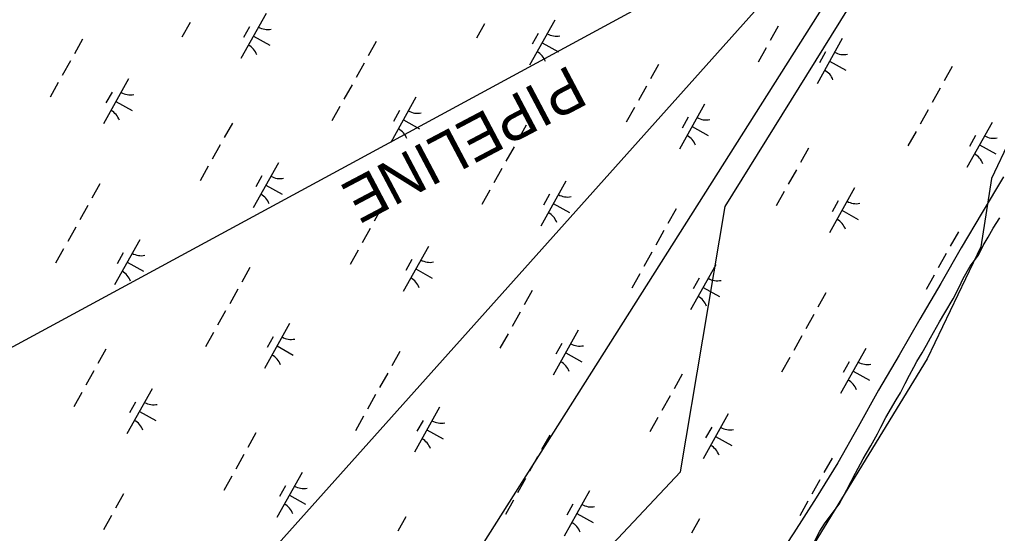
# Model space of a CAD drawing. Extents: x 3923531 to 3943530, y 207391 to 229799.
# Drawn here: x 3933623 to 3934571, y 218625 to 219123 of the extents above; entities that cross this region are included whole.
import ezdxf

# ---------------------------------------------------------------- set-up
doc = ezdxf.new("R2010")
doc.units = 0
for name, color, linetype in [('V-RIVR-EDGE', 7, 'Continuous'), ('V-RRAP-FSHR', 7, 'Continuous'), ('V-UTIL-IDEN', 7, 'Continuous'), ('V-UTIL-LINE', 7, 'Continuous'), ('V-WETL-SWMP', 7, 'Continuous')]:
    doc.layers.add(name, color=color, linetype=linetype)

msp = doc.modelspace()

# ---------------------------------------------------------------- linework, layer by layer
at = {"layer": 'V-RIVR-EDGE'}
msp.add_lwpolyline([(3934582.61, 219006.45), (3934564.92, 218968.73), (3934554.32, 218902.72), (3934502.45, 218794.28), (3934376.33, 218588)], dxfattribs=at)
at = {"layer": 'V-RRAP-FSHR'}
msp.add_lwpolyline([(3934576.29, 218970.39), (3934555.88, 218935.98), (3934535.47, 218901.58), (3934515.64, 218867.18), (3934495.48, 218832.55), (3934475.21, 218797.82), (3934455.37, 218763.92), (3934435.63, 218728.3), (3934415.91, 218693.5), (3934394.97, 218659.43), (3934373.4, 218625.75), (3934351.84, 218592.57)], dxfattribs=at)
at = {"layer": 'V-UTIL-LINE'}
for points in [[(3936636.37, 224015.9), (3936525.62, 224056.17), (3935321.28, 220766.16), (3935347.69, 220401.84), (3934871.29, 219561.15), (3934439.51, 219247.4), (3932085.86, 216616.76), (3928247.61, 212430.32)], [(3934948.13, 219998.51), (3933937.95, 218403.55), (3930512.92, 214727.55), (3928293.59, 212405.31)], [(3936739.29, 218357.68), (3936622.11, 218414.56), (3934986.4, 219548.1), (3933485.3, 218734.77), (3932851.99, 218820.89)], [(3928303.68, 212396.77), (3930529.58, 214712.48), (3934263.4, 218684.83), (3934306.77, 218941.79), (3934562.09, 219352.8), (3934805.1, 219208.23)]]:
    msp.add_lwpolyline(points, dxfattribs=at)
at = {"layer": 'V-WETL-SWMP'}
for p, q in [((3933862.12, 219128.66), (3933837.73, 219085.01)), ((3933788.45, 219119.9), (3933780.65, 219105.93)), ((3934073.65, 219118.64), (3934065.85, 219104.68)), ((3934141.74, 219122.18), (3934117.35, 219078.53)), ((3934358.19, 219116.56), (3934350.39, 219102.59)), ((3933846.12, 219115.84), (3933840.26, 219105.36)), ((3934125.74, 219109.36), (3934119.88, 219098.88)), ((3933684.24, 219103.71), (3933676.44, 219089.74)), ((3933849.93, 219106.83), (3933865.64, 219098.06)), ((3933968.78, 219101.63), (3933960.98, 219087.66)), ((3934129.55, 219100.36), (3934145.26, 219091.58)), ((3934420.15, 219104.37), (3934395.77, 219060.72)), ((3934346.49, 219095.61), (3934338.68, 219081.64)), ((3934404.15, 219091.55), (3934398.3, 219081.07)), ((3933672.54, 219082.76), (3933664.73, 219068.79)), ((3933957.08, 219080.68), (3933949.27, 219066.71)), ((3934242.27, 219079.42), (3934234.47, 219065.46)), ((3934407.96, 219082.55), (3934423.67, 219073.77)), ((3934526.82, 219077.34), (3934519.01, 219063.37)), ((3933660.83, 219061.81), (3933653.03, 219047.84)), ((3933728.92, 219065.35), (3933704.53, 219021.7)), ((3933945.37, 219059.72), (3933937.57, 219045.76)), ((3933712.92, 219052.52), (3933707.06, 219042.05)), ((3934230.57, 219058.47), (3934222.77, 219044.5)), ((3934515.11, 219056.39), (3934507.31, 219042.42)), ((3933716.73, 219043.52), (3933732.44, 219034.74)), ((3934007.33, 219047.54), (3933982.95, 219003.89)), ((3934286.95, 219041.06), (3934262.57, 218997.41)), ((3933933.67, 219038.77), (3933925.86, 219024.8)), ((3933991.33, 219034.71), (3933985.48, 219024.24)), ((3934218.86, 219037.52), (3934211.06, 219023.55)), ((3934503.41, 219035.44), (3934495.6, 219021.47)), ((3933829.45, 219022.59), (3933821.65, 219008.62)), ((3933995.14, 219025.71), (3934010.85, 219016.93)), ((3934270.95, 219028.23), (3934265.1, 219017.76)), ((3934565.37, 219023.25), (3934540.98, 218979.6)), ((3934114, 219020.5), (3934106.19, 219006.54)), ((3934274.76, 219019.23), (3934290.47, 219010.45)), ((3934491.7, 219014.48), (3934483.9, 219000.52)), ((3934549.36, 219010.42), (3934543.51, 218999.95)), ((3933817.75, 219001.64), (3933809.95, 218987.67)), ((3934102.29, 218999.55), (3934094.49, 218985.58)), ((3934387.49, 218998.3), (3934379.68, 218984.33)), ((3934553.17, 219001.42), (3934568.89, 218992.64)), ((3933874.13, 218984.22), (3933849.75, 218940.57)), ((3933806.04, 218980.68), (3933798.24, 218966.72)), ((3934090.59, 218978.6), (3934082.78, 218964.63)), ((3934375.78, 218977.35), (3934367.98, 218963.38)), ((3933858.13, 218971.4), (3933852.28, 218960.92)), ((3934152.55, 218966.41), (3934128.16, 218922.76)), ((3933701.18, 218963.67), (3933693.37, 218949.7)), ((3933861.94, 218962.4), (3933877.65, 218953.62)), ((3934078.88, 218957.65), (3934071.08, 218943.68)), ((3934364.08, 218956.4), (3934356.27, 218942.43)), ((3934432.17, 218959.93), (3934407.78, 218916.28)), ((3934136.54, 218953.59), (3934130.69, 218943.11)), ((3934416.16, 218947.11), (3934410.31, 218936.63)), ((3933689.47, 218942.72), (3933681.67, 218928.75)), ((3933974.67, 218941.46), (3933966.86, 218927.5)), ((3934140.35, 218944.59), (3934156.07, 218935.81)), ((3934259.21, 218939.38), (3934251.41, 218925.41)), ((3934419.97, 218938.11), (3934435.69, 218929.33)), ((3934566.31, 218920.74), (3934572.99, 218930.64)), ((3933677.77, 218921.76), (3933669.96, 218907.8)), ((3933962.96, 218920.51), (3933955.16, 218906.54)), ((3934247.51, 218918.43), (3934239.7, 218904.46)), ((3934561.43, 218912.02), (3934566.31, 218920.74)), ((3933739.73, 218909.58), (3933715.34, 218865.93)), ((3934532.7, 218917.18), (3934524.9, 218903.21)), ((3934556.76, 218903.89), (3934561.43, 218912.02)), ((3933666.06, 218900.81), (3933658.26, 218886.84)), ((3933951.26, 218899.56), (3933943.45, 218885.59)), ((3934019.35, 218903.1), (3933994.96, 218859.45)), ((3934552.09, 218894.77), (3934556.76, 218903.89)), ((3933723.72, 218896.75), (3933717.87, 218886.28)), ((3934003.34, 218890.27), (3933997.49, 218879.8)), ((3934235.8, 218897.48), (3934228, 218883.51)), ((3934521, 218896.22), (3934513.19, 218882.26)), ((3934544.2, 218883.89), (3934552.09, 218894.77)), ((3933727.53, 218887.75), (3933743.25, 218878.97)), ((3933846.39, 218882.54), (3933838.59, 218868.58)), ((3934007.15, 218881.27), (3934022.87, 218872.49)), ((3934297.76, 218885.29), (3934273.37, 218841.64)), ((3934537.3, 218872), (3934544.2, 218883.89)), ((3934224.1, 218876.52), (3934216.29, 218862.56)), ((3934281.76, 218872.46), (3934275.91, 218861.99)), ((3934509.29, 218875.27), (3934501.49, 218861.3)), ((3934533.42, 218863.47), (3934537.3, 218872)), ((3933834.69, 218861.59), (3933826.88, 218847.62)), ((3934285.57, 218863.46), (3934301.28, 218854.68)), ((3934527.72, 218852.36), (3934533.42, 218863.47)), ((3934119.88, 218860.34), (3934112.08, 218846.37)), ((3934404.42, 218858.26), (3934396.62, 218844.29)), ((3934519.61, 218838.89), (3934527.72, 218852.36)), ((3933822.98, 218840.64), (3933815.18, 218826.67)), ((3934108.18, 218839.39), (3934100.37, 218825.42)), ((3934392.72, 218837.3), (3934384.92, 218823.34)), ((3934514.54, 218830.17), (3934519.61, 218838.89)), ((3933884.94, 218828.45), (3933860.55, 218784.8)), ((3934505.8, 218814.51), (3934514.54, 218830.17)), ((3933811.28, 218819.69), (3933803.47, 218805.72)), ((3933868.94, 218815.63), (3933863.09, 218805.15)), ((3934096.47, 218818.44), (3934088.67, 218804.47)), ((3934164.56, 218821.97), (3934140.17, 218778.32)), ((3934381.01, 218816.35), (3934373.21, 218802.38)), ((3934501.74, 218807.38), (3934505.8, 218814.51)), ((3933872.75, 218806.63), (3933888.46, 218797.85)), ((3934148.56, 218809.15), (3934142.7, 218798.67)), ((3934442.97, 218804.16), (3934418.59, 218760.51)), ((3934497.48, 218799.85), (3934501.74, 218807.38)), ((3933707.06, 218803.5), (3933699.26, 218789.54)), ((3933991.6, 218801.42), (3933983.8, 218787.45)), ((3934152.37, 218800.15), (3934168.08, 218791.37)), ((3934369.31, 218795.4), (3934361.51, 218781.43)), ((3934492.61, 218791.53), (3934497.48, 218799.85)), ((3934426.97, 218791.34), (3934421.12, 218780.86)), ((3934485.49, 218778.24), (3934489.56, 218785.98)), ((3934489.56, 218785.98), (3934492.61, 218791.53)), ((3933695.36, 218782.55), (3933687.55, 218768.58)), ((3933979.9, 218780.47), (3933972.1, 218766.5)), ((3934265.09, 218779.22), (3934257.29, 218765.25)), ((3934430.78, 218782.34), (3934446.49, 218773.56)), ((3934481.03, 218770.32), (3934485.49, 218778.24)), ((3934476.55, 218761.19), (3934481.03, 218770.32)), ((3933683.65, 218761.6), (3933675.85, 218747.63)), ((3933751.74, 218765.14), (3933727.35, 218721.49)), ((3933968.19, 218759.52), (3933960.39, 218745.55)), ((3934253.39, 218758.26), (3934245.59, 218744.3)), ((3934472.29, 218754.46), (3934476.55, 218761.19)), ((3933735.74, 218752.31), (3933729.88, 218741.84)), ((3934030.15, 218747.33), (3934005.77, 218703.68)), ((3934462.34, 218737.22), (3934472.29, 218754.46)), ((3933739.55, 218743.31), (3933755.26, 218734.53)), ((3933956.49, 218738.56), (3933948.69, 218724.59)), ((3934309.77, 218740.85), (3934285.39, 218697.2)), ((3934014.15, 218734.5), (3934008.3, 218724.03)), ((3934241.68, 218737.31), (3934233.88, 218723.34)), ((3934457.66, 218727.9), (3934462.34, 218737.22)), ((3933852.27, 218722.38), (3933844.47, 218708.41)), ((3934017.96, 218725.5), (3934033.68, 218716.72)), ((3934136.82, 218720.3), (3934129.01, 218706.33)), ((3934293.77, 218728.03), (3934287.92, 218717.55)), ((3934297.58, 218719.02), (3934313.29, 218710.25)), ((3934447.91, 218709.86), (3934454.41, 218721.55)), ((3934454.41, 218721.55), (3934457.66, 218727.9)), ((3934440.6, 218697.38), (3934447.91, 218709.86)), ((3933840.57, 218701.43), (3933832.77, 218687.46)), ((3934125.11, 218699.34), (3934117.31, 218685.38)), ((3934410.31, 218698.09), (3934402.51, 218684.12)), ((3934433.08, 218683.3), (3934440.6, 218697.38)), ((3933896.95, 218684.01), (3933872.57, 218640.36)), ((3934424.54, 218667.44), (3934433.08, 218683.3)), ((3933828.86, 218680.48), (3933821.06, 218666.51)), ((3934113.41, 218678.39), (3934105.6, 218664.42)), ((3934398.6, 218677.14), (3934390.8, 218663.17)), ((3933724, 218663.46), (3933716.19, 218649.49)), ((3933880.95, 218671.19), (3933875.1, 218660.71)), ((3933884.76, 218662.19), (3933900.47, 218653.41)), ((3934175.37, 218666.2), (3934150.98, 218622.55)), ((3934417.22, 218653.56), (3934424.54, 218667.44)), ((3934101.7, 218657.44), (3934093.9, 218643.47)), ((3934159.37, 218653.38), (3934153.51, 218642.9)), ((3934386.9, 218656.19), (3934379.1, 218642.22)), ((3934410.35, 218644.26), (3934417.22, 218653.56)), ((3934163.17, 218644.38), (3934178.89, 218635.6)), ((3934402.87, 218634.37), (3934410.35, 218644.26)), ((3933712.29, 218642.51), (3933704.49, 218628.54)), ((3933997.49, 218641.26), (3933989.69, 218627.29)), ((3934282.03, 218639.17), (3934274.23, 218625.2)), ((3934398.61, 218627.24), (3934402.87, 218634.37)), ((3934393.32, 218617.33), (3934398.61, 218627.24))]:
    msp.add_line(p, q, dxfattribs=at)
for centre, start, end in [((3933863.6, 219130.83), 240.03808, 281.58174), ((3934143.22, 219124.36), 240.03808, 281.58174), ((3933836.66, 219082.61), 20.03808, 61.58174), ((3934116.28, 219076.13), 20.03808, 61.58174), ((3934421.64, 219106.54), 240.03808, 281.58174), ((3934394.7, 219058.32), 20.03808, 61.58174), ((3933730.4, 219067.52), 240.03808, 281.58174), ((3933703.46, 219019.29), 20.03808, 61.58174), ((3934008.82, 219049.71), 240.03808, 281.58174), ((3934288.44, 219043.23), 240.03808, 281.58174), ((3933981.88, 219001.48), 20.03808, 61.58174), ((3934261.5, 218995), 20.03808, 61.58174), ((3934566.85, 219025.42), 240.03808, 281.58174), ((3934539.91, 218977.19), 20.03808, 61.58174), ((3933875.62, 218986.4), 240.03808, 281.58174), ((3933848.68, 218938.17), 20.03808, 61.58174), ((3934154.03, 218968.58), 240.03808, 281.58174), ((3934433.65, 218962.11), 240.03808, 281.58174), ((3934127.09, 218920.36), 20.03808, 61.58174), ((3934406.71, 218913.88), 20.03808, 61.58174), ((3933741.21, 218911.75), 240.03808, 281.58174), ((3934020.83, 218905.27), 240.03808, 281.58174), ((3933714.27, 218863.52), 20.03808, 61.58174), ((3933993.89, 218857.04), 20.03808, 61.58174), ((3934299.25, 218887.46), 240.03808, 281.58174), ((3934272.3, 218839.23), 20.03808, 61.58174), ((3933886.43, 218830.62), 240.03808, 281.58174), ((3934166.05, 218824.15), 240.03808, 281.58174), ((3933859.48, 218782.4), 20.03808, 61.58174), ((3934139.1, 218775.92), 20.03808, 61.58174), ((3934444.46, 218806.34), 240.03808, 281.58174), ((3934417.52, 218758.11), 20.03808, 61.58174), ((3933753.23, 218767.31), 240.03808, 281.58174), ((3933726.28, 218719.08), 20.03808, 61.58174), ((3934031.64, 218749.5), 240.03808, 281.58174), ((3934311.26, 218743.02), 240.03808, 281.58174), ((3934004.7, 218701.27), 20.03808, 61.58174), ((3934284.32, 218694.8), 20.03808, 61.58174), ((3933898.44, 218686.19), 240.03808, 281.58174), ((3933871.5, 218637.96), 20.03808, 61.58174), ((3934176.85, 218668.38), 240.03808, 281.58174), ((3934149.91, 218620.15), 20.03808, 61.58174)]:
    msp.add_arc(centre, 17.62, start, end, dxfattribs=at)

# ---------------------------------------------------------------- texts
at = {"layer": 'V-UTIL-IDEN'}
msp.add_text('PIPELINE', height=42, rotation=207.85616, dxfattribs=at).set_placement((3934156.24, 219079.48))

doc.saveas('drawing.dxf')
